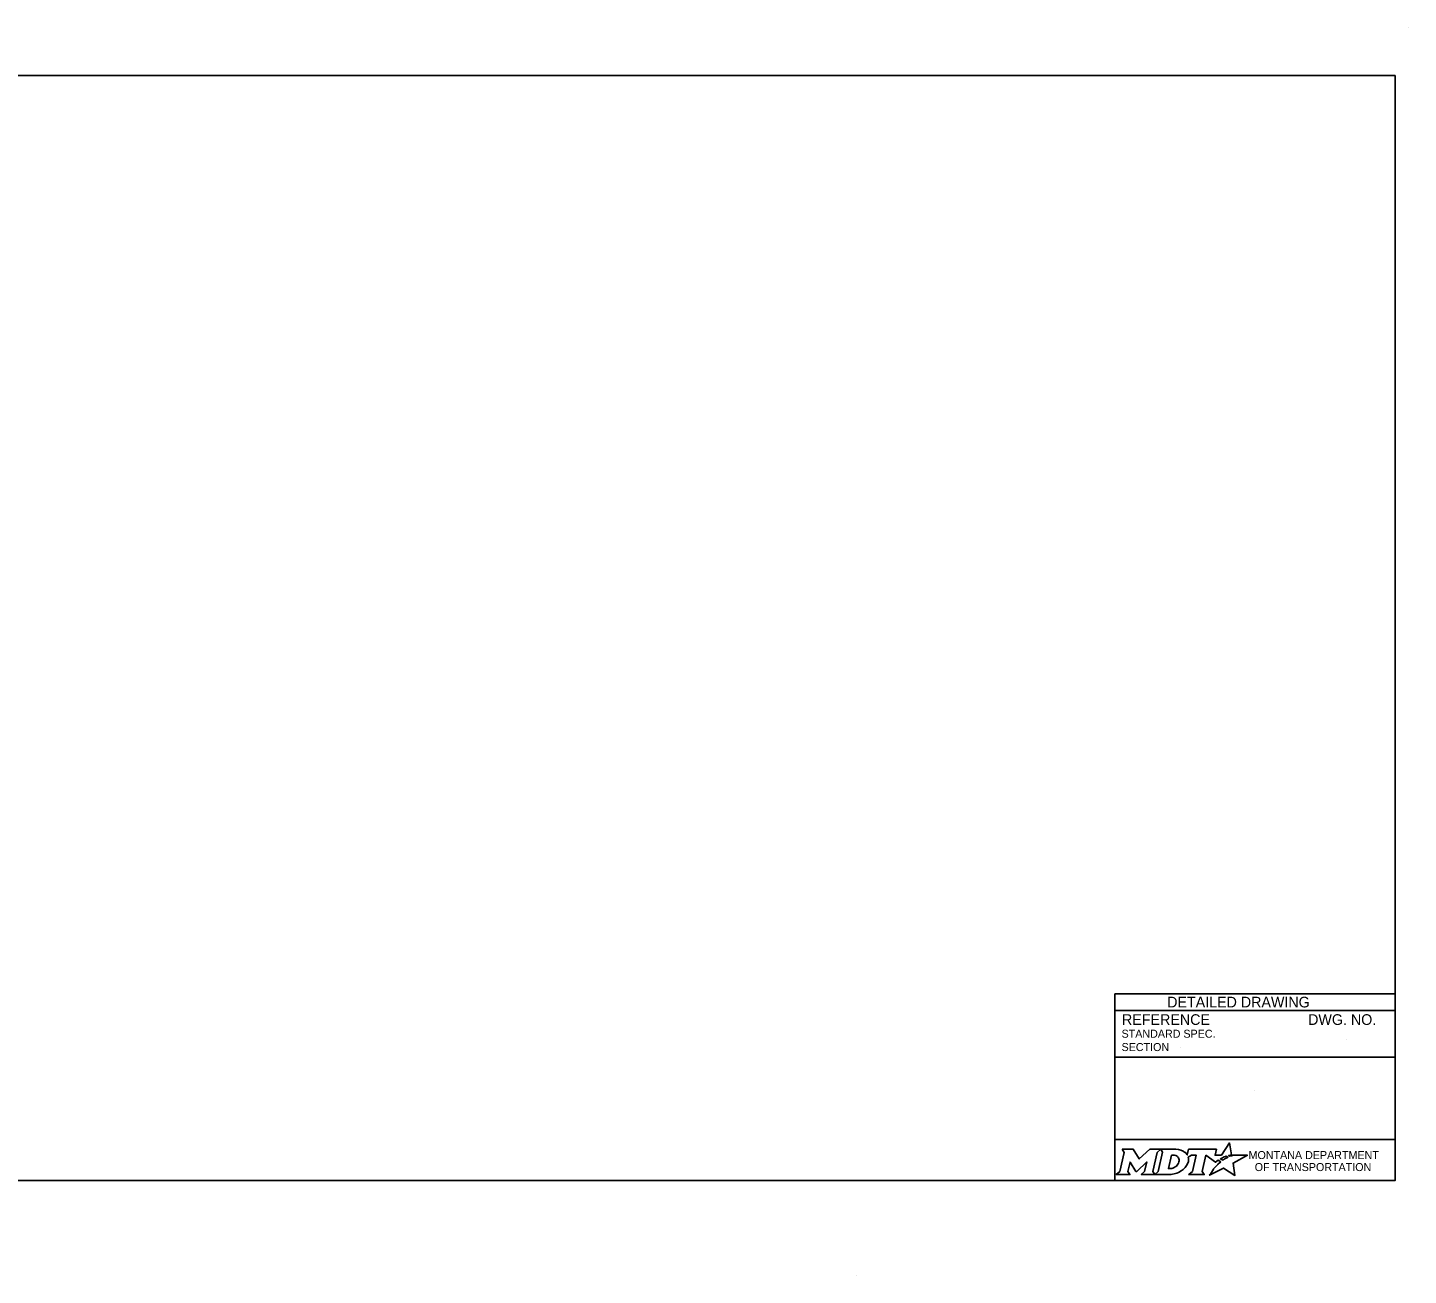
# Model space of a CAD drawing. Extents: x 49991.4 to 50021, y 49987.6 to 50011.4.
# Drawn here: x 50010.69 to 50021.04, y 49999.18 to 50008.52 of the extents above; entities that cross this region are included whole.
import ezdxf

# ---------------------------------------------------------------- set-up
doc = ezdxf.new("R2010")
doc.units = 0
for name, color, linetype in [('Default', 7, 'Continuous'), ('Level 1', 7, 'Continuous'), ('Level 4', 7, 'Continuous')]:
    doc.layers.add(name, color=color, linetype=linetype)

msp = doc.modelspace()

# ---------------------------------------------------------------- linework, layer by layer
at = {"layer": 'Default'}
for points in [[(50019.7, 50000.068), (50019.69, 50000.074), (50019.702, 50000.076), (50019.713, 50000.078), (50019.696, 50000.168), (50019.636, 50000.077), (50019.589, 50000.076), (50019.599, 50000.12), (50019.39, 50000.121), (50019.38, 50000.078), (50019.374, 50000.086)], [(50018.893, 50000.121), (50018.907, 50000.097), (50018.874, 49999.954), (50018.848, 49999.931), (50018.95, 49999.931), (50018.936, 49999.954), (50018.952, 50000.024), (50018.996, 49999.955), (50019.002, 49999.955), (50019.077, 50000.025), (50019.06, 49999.954), (50019.035, 49999.932), (50019.137, 49999.932), (50019.123, 49999.955), (50019.156, 50000.097)], [(50019.156, 50000.097), (50019.182, 50000.121), (50019.099, 50000.121), (50019.02, 50000.048), (50018.975, 50000.12), (50018.893, 50000.121)], [(50019.295, 50000.121), (50019.182, 50000.121), (50019.196, 50000.098), (50019.163, 49999.954), (50019.137, 49999.932), (50019.248, 49999.932)], [(50019.319, 50000.034), (50019.318, 50000.026), (50019.315, 50000.017), (50019.311, 50000.008), (50019.305, 50000.001), (50019.299, 49999.994), (50019.291, 49999.988), (50019.282, 49999.983), (50019.273, 49999.979), (50019.264, 49999.977), (50019.255, 49999.976), (50019.239, 49999.976), (50019.263, 50000.076), (50019.279, 50000.076), (50019.286, 50000.075), (50019.294, 50000.073), (50019.301, 50000.07), (50019.307, 50000.066), (50019.311, 50000.061), (50019.315, 50000.055), (50019.318, 50000.049), (50019.319, 50000.042), (50019.32, 50000.038), (50019.319, 50000.034)], [(50019.387, 50000.062), (50019.411, 50000.075), (50019.448, 50000.075), (50019.42, 49999.954), (50019.392, 49999.931), (50019.508, 49999.931), (50019.491, 49999.954), (50019.52, 50000.075), (50019.591, 50000.023), (50019.612, 50000.038), (50019.632, 50000.027)], [(50019.576, 49999.971), (50019.561, 49999.947), (50019.556, 49999.939), (50019.55, 49999.931), (50019.548, 49999.926), (50019.653, 49999.979), (50019.737, 49999.924), (50019.724, 50000.017), (50019.831, 50000.075), (50019.782, 50000.076), (50019.751, 50000.077), (50019.731, 50000.077), (50019.724, 50000.075), (50019.719, 50000.074), (50019.711, 50000.072), (50019.7, 50000.068)], [(50019.65, 50000.04), (50019.648, 50000.039), (50019.629, 50000.048), (50019.639, 50000.054), (50019.644, 50000.056), (50019.652, 50000.06), (50019.658, 50000.063), (50019.666, 50000.066), (50019.673, 50000.068), (50019.685, 50000.061), (50019.681, 50000.059), (50019.676, 50000.056), (50019.672, 50000.054), (50019.667, 50000.051), (50019.665, 50000.05), (50019.662, 50000.049), (50019.66, 50000.047), (50019.658, 50000.046), (50019.655, 50000.044), (50019.652, 50000.042), (50019.65, 50000.04)], [(50019.59, 49999.987), (50019.59, 49999.987)], [(50019.293, 49999.939), (50019.302, 49999.942), (50019.315, 49999.947), (50019.335, 49999.958)]]:
    msp.add_lwpolyline(points, dxfattribs=at)
for centre, radius, start, end in [((50019.274, 50000.059), 0.118, 300.9103, 339.1383), ((50019.319, 50000.042), 0.0709, 339.5329, 15.8582)]:
    msp.add_arc(centre, radius, start, end, dxfattribs=at)
for centre, major_axis, ratio, start_param, end_param in [((50019.293, 50000.073), (0.0834, -0.0037), 0.568097, 0.61298, 1.570796), ((50019.349, 50000.081), (0.0361, -0.0295), 0.469099, 1.225588, 1.570796), ((50019.583, 49999.979), (-0.00694, -0.00806), 0.008222, 0, 3.137361), ((50019.6, 49999.997), (-0.0098, -0.0102), 0.016458, 3.141593, 6.279097), ((50019.621, 50000.017), (-0.0112, -0.0097), 0.021651, 3.157348, 6.283185), ((50019.248, 50000.08), (0, 0.148), 0.987302, 3.139398, 3.456847)]:
    msp.add_ellipse(centre, major_axis=major_axis, ratio=ratio, start_param=start_param, end_param=end_param, dxfattribs=at)
at = {"layer": 'Level 1'}
for p, q in [((50021.038, 50008.524), (50021.038, 50008.524)), ((50016.9, 49999.176), (50016.9, 49999.176))]:
    msp.add_line(p, q, dxfattribs=at)
msp.add_lwpolyline([(50020.938, 50008.165), (50009.737, 50008.165), (50009.737, 49999.886), (50020.938, 49999.886)], close=True, dxfattribs=at)
at = {"layer": 'Level 4'}
for p, q in [((50020.938, 50001.286), (50018.838, 50001.286)), ((50018.838, 50001.286), (50018.838, 49999.886)), ((50020.938, 50001.161), (50018.838, 50001.161)), ((50020.574, 50000.946), (50020.574, 50000.946)), ((50020.938, 50000.811), (50018.838, 50000.811)), ((50019.332, 50000.886), (50019.332, 50000.886)), ((50019.888, 50000.562), (50019.888, 50000.562)), ((50020.938, 50000.193), (50018.838, 50000.193))]:
    msp.add_line(p, q, dxfattribs=at)

# ---------------------------------------------------------------- texts
at = {"layer": 'Default'}
for s, p in [('MONTANA DEPARTMENT', (50019.84, 50000.047)), ('OF TRANSPORTATION', (50019.886, 49999.957))]:
    msp.add_text(s, height=0.06, rotation=360, dxfattribs=at).set_placement(p)
at = {"layer": 'Level 4'}
for s, height, p in [('DETAILED DRAWING', 0.0799, (50019.23, 50001.183)), ('REFERENCE', 0.08, (50018.891, 50001.052)), ('DWG. NO.', 0.08, (50020.286, 50001.052)), ('STANDARD SPEC.', 0.06, (50018.888, 50000.956)), ('SECTION', 0.06, (50018.888, 50000.856))]:
    msp.add_text(s, height=height, dxfattribs=at).set_placement(p)

doc.saveas('drawing.dxf')
